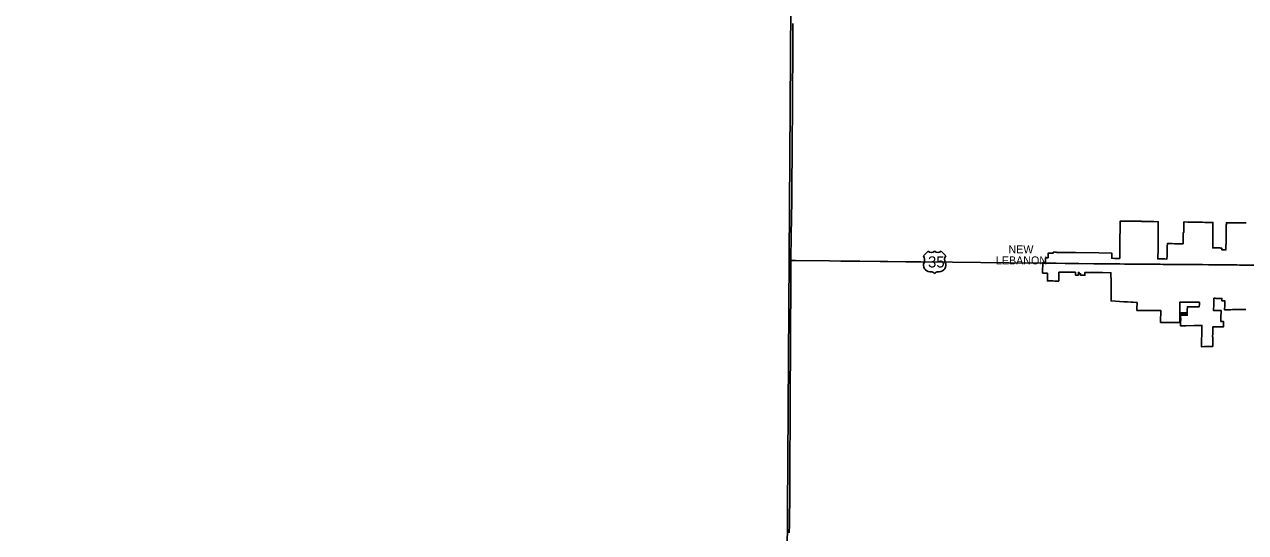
# Model space of a CAD drawing. Extents: x 0 to 34, y 0 to 22.
# Drawn here: x 3.218 to 4.445, y 14.836 to 15.346 of the extents above; entities that cross this region are included whole.
import ezdxf

# ---------------------------------------------------------------- set-up
doc = ezdxf.new("R2010")
doc.units = 0
for name, color, linetype in [('GM_X_Corporation', 7, 'Continuous'), ('GM_X_Corporation_Text', 7, 'Continuous'), ('GM_X_County', 7, 'Continuous'), ('GM_X_US_Location', 7, 'Continuous'), ('GM_X_US_Route', 7, 'Continuous'), ('GM_X_US_Shield', 7, 'Continuous'), ('SC_Scratch1', 7, 'Continuous')]:
    doc.layers.add(name, color=color, linetype=linetype)

msp = doc.modelspace()

# ---------------------------------------------------------------- linework, layer by layer
at = {"layer": 'GM_X_Corporation'}
msp.add_lwpolyline([(4.4448, 15.0596), (4.4439, 15.0596), (4.4411, 15.0596), (4.4405, 15.0596), (4.4388, 15.0595), (4.4359, 15.0595), (4.4347, 15.0595), (4.4316, 15.0595), (4.4296, 15.0594), (4.4268, 15.0594), (4.4242, 15.0594), (4.4235, 15.0594), (4.4236, 15.0597), (4.4237, 15.0632), (4.4237, 15.0647), (4.4238, 15.0678), (4.4238, 15.0682), (4.4235, 15.0682), (4.4233, 15.0682), (4.4208, 15.0683), (4.4208, 15.0683), (4.4209, 15.0707), (4.4198, 15.0707), (4.4186, 15.0708), (4.4181, 15.0708), (4.4175, 15.0708), (4.4163, 15.0708), (4.4152, 15.0708), (4.414, 15.0709), (4.4138, 15.0709), (4.4129, 15.0709), (4.4128, 15.0699), (4.4128, 15.0687), (4.4128, 15.0685), (4.4128, 15.0684), (4.4127, 15.0674), (4.4127, 15.0661), (4.4127, 15.0661), (4.4127, 15.0656), (4.4126, 15.0649), (4.4126, 15.064), (4.4126, 15.0636), (4.4126, 15.0624), (4.4125, 15.0611), (4.4125, 15.0605), (4.4125, 15.0599), (4.4124, 15.0587), (4.4126, 15.0587), (4.4135, 15.0587), (4.4136, 15.0587), (4.4142, 15.0587), (4.415, 15.0587), (4.4158, 15.0587), (4.4166, 15.0587), (4.4174, 15.0587), (4.4187, 15.0587), (4.4201, 15.0587), (4.4201, 15.0587), (4.4201, 15.0587), (4.4201, 15.0585), (4.42, 15.0575), (4.42, 15.0572), (4.42, 15.0571), (4.42, 15.0558), (4.42, 15.0555), (4.4199, 15.054), (4.4199, 15.0531), (4.4199, 15.0523), (4.4199, 15.0511), (4.4198, 15.0507), (4.4198, 15.0498), (4.4198, 15.0489), (4.4198, 15.0474), (4.4198, 15.0474), (4.4209, 15.0474), (4.4213, 15.0474), (4.4225, 15.0474), (4.4226, 15.0474), (4.4225, 15.0423), (4.4223, 15.0423), (4.4206, 15.0423), (4.4193, 15.0423), (4.4192, 15.0423), (4.418, 15.0423), (4.4167, 15.0423), (4.4154, 15.0423), (4.4141, 15.0423), (4.4118, 15.0423), (4.4117, 15.0411), (4.4117, 15.0391), (4.4116, 15.0363), (4.4116, 15.0361), (4.4116, 15.0357), (4.4115, 15.032), (4.4119, 15.032), (4.4118, 15.0299), (4.4117, 15.028), (4.4117, 15.0276), (4.4117, 15.0247), (4.4116, 15.0239), (4.4116, 15.0225), (4.411, 15.0225), (4.4086, 15.0225), (4.4033, 15.0223), (4.4003, 15.0222), (4.4004, 15.0238), (4.4004, 15.0241), (4.4005, 15.0275), (4.4005, 15.0308), (4.4006, 15.0329), (4.4006, 15.0344), (4.4008, 15.0436), (4.4008, 15.0436), (4.3986, 15.0436), (4.3957, 15.0435), (4.3931, 15.0434), (4.3846, 15.0432), (4.3793, 15.0431), (4.3793, 15.0431), (4.3793, 15.0442), (4.3793, 15.045), (4.3794, 15.0466), (4.3794, 15.0469), (4.3795, 15.0495), (4.3795, 15.0504), (4.3794, 15.0518), (4.3795, 15.0533), (4.3795, 15.0537), (4.3795, 15.0538), (4.3819, 15.0538), (4.3851, 15.0538), (4.386, 15.0538), (4.386, 15.0555), (4.3851, 15.0555), (4.3815, 15.0556), (4.3795, 15.0556), (4.3795, 15.0556), (4.3795, 15.0563), (4.3795, 15.0564), (4.3812, 15.0564), (4.3859, 15.0563), (4.3861, 15.0563), (4.3861, 15.0565), (4.3861, 15.0595), (4.3862, 15.062), (4.3862, 15.0624), (4.3881, 15.0624), (4.3895, 15.0624), (4.3933, 15.0624), (4.3968, 15.0624), (4.3981, 15.0624), (4.3981, 15.0627), (4.3981, 15.0633), (4.3981, 15.0635), (4.3982, 15.0638), (4.3982, 15.0649), (4.3982, 15.0653), (4.3982, 15.0661), (4.3982, 15.0669), (4.3972, 15.0669), (4.3963, 15.0669), (4.3954, 15.0669), (4.3947, 15.0669), (4.3941, 15.0669), (4.393, 15.0669), (4.3927, 15.0669), (4.3918, 15.0669), (4.3906, 15.0669), (4.3905, 15.0669), (4.3894, 15.0669), (4.3882, 15.0669), (4.3871, 15.0669), (4.3859, 15.0669), (4.3847, 15.0669), (4.384, 15.0669), (4.3835, 15.0669), (4.3823, 15.067), (4.3812, 15.067), (4.3811, 15.067), (4.3797, 15.067), (4.3792, 15.067), (4.3787, 15.067), (4.3787, 15.0669), (4.3787, 15.0656), (4.3787, 15.0624), (4.3787, 15.0622), (4.3787, 15.0621), (4.3787, 15.0619), (4.3787, 15.0611), (4.3787, 15.0608), (4.3787, 15.0595), (4.3786, 15.0587), (4.3786, 15.0587), (4.3786, 15.0565), (4.3786, 15.0565), (4.3785, 15.055), (4.3785, 15.0544), (4.3785, 15.0537), (4.3785, 15.0533), (4.3785, 15.0525), (4.3785, 15.0518), (4.3785, 15.0504), (4.3785, 15.0495), (4.3785, 15.0494), (4.3785, 15.0494), (4.3785, 15.0494), (4.3785, 15.0488), (4.3785, 15.0488), (4.3785, 15.0482), (4.3785, 15.0482), (4.3785, 15.0482), (4.3784, 15.0466), (4.3767, 15.0466), (4.3761, 15.0466), (4.3754, 15.0466), (4.3747, 15.0466), (4.3741, 15.0466), (4.3733, 15.0466), (4.3729, 15.0466), (4.3724, 15.0466), (4.3714, 15.0466), (4.3706, 15.0466), (4.3687, 15.0466), (4.3663, 15.0466), (4.364, 15.0466), (4.3621, 15.0466), (4.3617, 15.0466), (4.3601, 15.0466), (4.3593, 15.0466), (4.3592, 15.0466), (4.3593, 15.0474), (4.3593, 15.0475), (4.3593, 15.0492), (4.3593, 15.05), (4.3593, 15.0511), (4.3593, 15.0523), (4.3594, 15.0535), (4.3594, 15.0542), (4.3594, 15.0546), (4.3594, 15.0559), (4.3594, 15.0564), (4.3594, 15.0568), (4.3594, 15.0587), (4.3594, 15.0587), (4.3587, 15.0587), (4.3569, 15.0587), (4.3548, 15.0587), (4.3527, 15.0587), (4.3519, 15.0587), (4.3504, 15.0587), (4.3492, 15.0587), (4.348, 15.0587), (4.3462, 15.0587), (4.3449, 15.0587), (4.3446, 15.0587), (4.3401, 15.0587), (4.3385, 15.0587), (4.3355, 15.0587), (4.3355, 15.0629), (4.3355, 15.0634), (4.3356, 15.0636), (4.3356, 15.0649), (4.3356, 15.0659), (4.3356, 15.0666), (4.3356, 15.0666), (4.3354, 15.0666), (4.3354, 15.0667), (4.3349, 15.0667), (4.3349, 15.0667), (4.3317, 15.0669), (4.3296, 15.067), (4.3259, 15.0672), (4.3223, 15.0674), (4.3095, 15.0682), (4.3095, 15.0771), (4.3095, 15.0893), (4.3095, 15.0901), (4.3094, 15.093), (4.3094, 15.095), (4.3094, 15.0966), (4.3011, 15.0967), (4.301, 15.0967), (4.2927, 15.0968), (4.2893, 15.0968), (4.2892, 15.0968), (4.2832, 15.0969), (4.2832, 15.0967), (4.2832, 15.094), (4.2791, 15.094), (4.2789, 15.094), (4.2789, 15.0953), (4.2789, 15.0955), (4.2776, 15.0955), (4.2775, 15.0955), (4.2775, 15.0963), (4.2775, 15.0968), (4.2775, 15.0969), (4.2774, 15.0969), (4.2771, 15.0969), (4.277, 15.0969), (4.2767, 15.097), (4.2767, 15.097), (4.2767, 15.0968), (4.2767, 15.0963), (4.2767, 15.0941), (4.2766, 15.0941), (4.2738, 15.0941), (4.2738, 15.0969), (4.2738, 15.097), (4.2733, 15.097), (4.2732, 15.097), (4.2699, 15.097), (4.2699, 15.097), (4.2679, 15.097), (4.2663, 15.097), (4.2663, 15.097), (4.2572, 15.0971), (4.2572, 15.097), (4.2572, 15.0967), (4.2572, 15.0963), (4.2571, 15.0925), (4.257, 15.0882), (4.2534, 15.0882), (4.253, 15.0882), (4.2509, 15.0883), (4.2504, 15.0883), (4.2499, 15.0883), (4.2456, 15.0883), (4.2457, 15.0951), (4.2457, 15.0961), (4.2427, 15.0961), (4.2426, 15.0961), (4.2408, 15.0962), (4.2407, 15.0962), (4.2408, 15.098), (4.241, 15.1056), (4.241, 15.1057), (4.241, 15.1062), (4.241, 15.1068), (4.2436, 15.1068), (4.2437, 15.1116), (4.2442, 15.1116), (4.2451, 15.1116), (4.2463, 15.1116), (4.2463, 15.112), (4.2464, 15.1162), (4.2464, 15.1163), (4.2465, 15.1163), (4.2476, 15.1163), (4.2503, 15.1163), (4.2514, 15.1163), (4.2514, 15.117), (4.2514, 15.1171), (4.2541, 15.1171), (4.2545, 15.1171), (4.255, 15.117), (4.2576, 15.117), (4.2585, 15.117), (4.2636, 15.1169), (4.2646, 15.1169), (4.2647, 15.1169), (4.2657, 15.1169), (4.2668, 15.1169), (4.2678, 15.1169), (4.2699, 15.1168), (4.2726, 15.1168), (4.2739, 15.1168), (4.2971, 15.1165), (4.3103, 15.1163), (4.3103, 15.1162), (4.3103, 15.1162), (4.3102, 15.111), (4.3106, 15.111), (4.3131, 15.1109), (4.3146, 15.1109), (4.3147, 15.1109), (4.3163, 15.1109), (4.3182, 15.1109), (4.3182, 15.112), (4.3184, 15.1215), (4.3184, 15.124), (4.3184, 15.1269), (4.3185, 15.1294), (4.3185, 15.1311), (4.3185, 15.1344), (4.3186, 15.1374), (4.3186, 15.1413), (4.3186, 15.1429), (4.3187, 15.1459), (4.3187, 15.1481), (4.3187, 15.1484), (4.3192, 15.1484), (4.3228, 15.1484), (4.3244, 15.1484), (4.3263, 15.1483), (4.3287, 15.1483), (4.329, 15.1483), (4.3298, 15.1483), (4.3329, 15.1483), (4.3352, 15.1483), (4.3381, 15.1482), (4.34, 15.1482), (4.34, 15.1482), (4.34, 15.1482), (4.34, 15.1481), (4.34, 15.1481), (4.3432, 15.148), (4.3439, 15.148), (4.3477, 15.148), (4.3493, 15.1479), (4.3525, 15.1479), (4.357, 15.1478), (4.357, 15.1478), (4.3569, 15.1405), (4.3568, 15.1359), (4.3568, 15.1351), (4.3568, 15.1324), (4.3568, 15.1309), (4.3567, 15.1212), (4.3567, 15.1209), (4.3565, 15.1105), (4.3565, 15.1104), (4.3565, 15.1104), (4.3601, 15.1104), (4.3602, 15.1104), (4.363, 15.1104), (4.3634, 15.1104), (4.3657, 15.1103), (4.3658, 15.114), (4.3658, 15.1151), (4.3659, 15.1181), (4.366, 15.1211), (4.366, 15.1229), (4.3661, 15.1258), (4.371, 15.1258), (4.3732, 15.1257), (4.3749, 15.1257), (4.3776, 15.1257), (4.3803, 15.1256), (4.3815, 15.1256), (4.3816, 15.1256), (4.3818, 15.1256), (4.3819, 15.1256), (4.382, 15.1369), (4.3823, 15.1369), (4.3826, 15.1369), (4.3826, 15.1415), (4.3827, 15.1475), (4.383, 15.1475), (4.3831, 15.1475), (4.3867, 15.1474), (4.3882, 15.1474), (4.3898, 15.1474), (4.3916, 15.1473), (4.3956, 15.1473), (4.3972, 15.1472), (4.3973, 15.1472), (4.3982, 15.1472), (4.4012, 15.1472), (4.4036, 15.1471), (4.4091, 15.1471), (4.4119, 15.147), (4.4119, 15.1469), (4.4119, 15.1464), (4.4119, 15.142), (4.4118, 15.1355), (4.4118, 15.1345), (4.4118, 15.1324), (4.4118, 15.1322), (4.4118, 15.1289), (4.4118, 15.1282), (4.4118, 15.1251), (4.4117, 15.1214), (4.4119, 15.1214), (4.4125, 15.1214), (4.4127, 15.1214), (4.4135, 15.1214), (4.4139, 15.1214), (4.4142, 15.1214), (4.4143, 15.1214), (4.4151, 15.1214), (4.4159, 15.1214), (4.4167, 15.1214), (4.4171, 15.1214), (4.4174, 15.1214), (4.4175, 15.1214), (4.4183, 15.1214), (4.4191, 15.1214), (4.4195, 15.1213), (4.4199, 15.1213), (4.4207, 15.1213), (4.4207, 15.1213), (4.4207, 15.1196), (4.4216, 15.1196), (4.4219, 15.1196), (4.4231, 15.1195), (4.4248, 15.1195), (4.4248, 15.1222), (4.4249, 15.1229), (4.4249, 15.1229), (4.4249, 15.1241), (4.4249, 15.1248), (4.425, 15.1249), (4.425, 15.1257), (4.425, 15.1262), (4.425, 15.1271), (4.425, 15.1292), (4.4251, 15.1311), (4.4251, 15.1322), (4.4251, 15.1333), (4.4251, 15.1336), (4.4251, 15.1365), (4.4251, 15.1379), (4.4252, 15.1414), (4.4252, 15.1433), (4.4252, 15.1444), (4.4253, 15.1452), (4.4253, 15.1468), (4.4293, 15.1468), (4.4301, 15.1468), (4.4347, 15.1467), (4.4367, 15.1467), (4.4389, 15.1467), (4.4436, 15.1466), (4.4452, 15.1466)], dxfattribs=at)
msp.add_lwpolyline([(4.4119, 15.147), (4.4119, 15.147), (4.4119, 15.147)], close=True, dxfattribs=at)
at = {"layer": 'GM_X_County'}
msp.add_lwpolyline([(3.9864, 14.8354), (3.9864, 14.8363), (3.9864, 14.8371), (3.9864, 14.8385), (3.9865, 14.8403), (3.9865, 14.8413), (3.9865, 14.8445), (3.9866, 14.848), (3.9866, 14.8504), (3.9866, 14.8523), (3.9866, 14.8525), (3.9866, 14.853), (3.9867, 14.8548), (3.9867, 14.8566), (3.9867, 14.858), (3.9867, 14.8592), (3.9868, 14.8606), (3.9868, 14.8615), (3.9868, 14.862), (3.9868, 14.8647), (3.9868, 14.8658), (3.9868, 14.8681), (3.9869, 14.8695), (3.9869, 14.8715), (3.9869, 14.8752), (3.9869, 14.8782), (3.9869, 14.8818), (3.9869, 14.8828), (3.9869, 14.8841), (3.9869, 14.8861), (3.9869, 14.8877), (3.9869, 14.8894), (3.9869, 14.8903), (3.9869, 14.8915), (3.9869, 14.8931), (3.9869, 14.8946), (3.9869, 14.895), (3.9869, 14.8978), (3.9869, 14.8987), (3.987, 14.9005), (3.987, 14.9018), (3.987, 14.903), (3.987, 14.9042), (3.987, 14.9054), (3.987, 14.9066), (3.987, 14.9072), (3.987, 14.9087), (3.987, 14.9104), (3.987, 14.9127), (3.987, 14.9152), (3.987, 14.9174), (3.9871, 14.9223), (3.9871, 14.9235), (3.9871, 14.9251), (3.9871, 14.927), (3.9872, 14.9292), (3.9872, 14.9317), (3.9872, 14.9326), (3.9872, 14.9341), (3.9872, 14.9354), (3.9872, 14.9365), (3.9872, 14.9389), (3.9872, 14.9397), (3.9872, 14.9414), (3.9872, 14.9426), (3.9872, 14.9434), (3.9872, 14.9449), (3.9872, 14.9461), (3.9872, 14.947), (3.9873, 14.9488), (3.9873, 14.9506), (3.9873, 14.9521), (3.9873, 14.953), (3.9873, 14.9542), (3.9873, 14.9554), (3.9873, 14.9571), (3.9873, 14.9591), (3.9873, 14.9599), (3.9873, 14.962), (3.9873, 14.9638), (3.9873, 14.9643), (3.9873, 14.9653), (3.9873, 14.9671), (3.9874, 14.9683), (3.9874, 14.9698), (3.9874, 14.971), (3.9874, 14.9722), (3.9874, 14.9734), (3.9874, 14.9744), (3.9874, 14.9756), (3.9874, 14.9767), (3.9874, 14.9777), (3.9874, 14.9787), (3.9874, 14.9797), (3.9874, 14.9798), (3.9874, 14.98), (3.9874, 14.9802), (3.9874, 14.9811), (3.9874, 14.9818), (3.9874, 14.9845), (3.9874, 14.9862), (3.9874, 14.9879), (3.9874, 14.9891), (3.9874, 14.9913), (3.9874, 14.9927), (3.9874, 14.9957), (3.9874, 14.9969), (3.9875, 14.9986), (3.9875, 14.9998), (3.9875, 15.0005), (3.9875, 15.0025), (3.9875, 15.0038), (3.9875, 15.0047), (3.9876, 15.0065), (3.9876, 15.0081), (3.9876, 15.0092), (3.9876, 15.011), (3.9876, 15.0127), (3.9876, 15.0139), (3.9876, 15.0154), (3.9876, 15.0164), (3.9876, 15.0186), (3.9877, 15.0206), (3.9877, 15.022), (3.9876, 15.0239), (3.9876, 15.0255), (3.9876, 15.0283), (3.9876, 15.0304), (3.9876, 15.0313), (3.9876, 15.0333), (3.9876, 15.035), (3.9876, 15.0361), (3.9876, 15.0382), (3.9876, 15.0394), (3.9876, 15.0425), (3.9876, 15.0434), (3.9877, 15.0453), (3.9877, 15.0471), (3.9877, 15.0518), (3.9877, 15.0532), (3.9877, 15.0546), (3.9877, 15.0558), (3.9877, 15.0568), (3.9877, 15.0586), (3.9877, 15.0598), (3.9878, 15.0605), (3.9878, 15.0633), (3.9878, 15.065), (3.9878, 15.0658), (3.9878, 15.0677), (3.9878, 15.0699), (3.9878, 15.0738), (3.9878, 15.0747), (3.9878, 15.0757), (3.9878, 15.0764), (3.9878, 15.0772), (3.9878, 15.079), (3.9878, 15.0803), (3.9878, 15.0815), (3.9879, 15.0838), (3.9879, 15.0859), (3.9879, 15.0875), (3.9879, 15.089), (3.9879, 15.0905), (3.988, 15.0952), (3.988, 15.0988), (3.988, 15.1041), (3.988, 15.106), (3.988, 15.1073), (3.988, 15.109), (3.988, 15.1101), (3.988, 15.1114), (3.988, 15.1128), (3.9881, 15.1142), (3.9881, 15.1163), (3.9881, 15.1173), (3.9881, 15.12), (3.9882, 15.124), (3.9882, 15.1247), (3.9882, 15.1265), (3.9882, 15.1279), (3.9882, 15.1291), (3.9883, 15.1339), (3.9884, 15.1388), (3.9884, 15.1405), (3.9884, 15.1421), (3.9885, 15.1435), (3.9885, 15.1461), (3.9885, 15.1469), (3.9886, 15.149), (3.9886, 15.1508), (3.9886, 15.155), (3.9887, 15.1563), (3.9887, 15.1582), (3.9888, 15.1621), (3.9888, 15.1671), (3.9888, 15.1701), (3.9889, 15.1718), (3.9889, 15.1742), (3.9889, 15.1765), (3.9889, 15.1773), (3.9889, 15.1819), (3.989, 15.1846), (3.989, 15.1868), (3.989, 15.1895), (3.989, 15.1906), (3.989, 15.1933), (3.989, 15.1938), (3.9891, 15.1946), (3.9891, 15.1955), (3.9891, 15.198), (3.9891, 15.1994), (3.9891, 15.2004), (3.9892, 15.2023), (3.9892, 15.2042), (3.9892, 15.2059), (3.9892, 15.2076), (3.9892, 15.2086), (3.9892, 15.2106), (3.9892, 15.212), (3.9893, 15.2142), (3.9893, 15.2148), (3.9893, 15.2168), (3.9893, 15.2185), (3.9893, 15.2212), (3.9893, 15.2232), (3.9893, 15.228), (3.9894, 15.2324), (3.9894, 15.2366), (3.9894, 15.2414), (3.9894, 15.2433), (3.9895, 15.2454), (3.9895, 15.2465), (3.9895, 15.2506), (3.9895, 15.252), (3.9895, 15.2539), (3.9895, 15.2556), (3.9895, 15.2574), (3.9896, 15.2589), (3.9896, 15.2596), (3.9896, 15.2629), (3.9896, 15.2664), (3.9896, 15.2713), (3.9897, 15.2735), (3.9897, 15.2751), (3.9897, 15.2776), (3.9897, 15.2793), (3.9897, 15.2799), (3.9897, 15.2816), (3.9897, 15.2833), (3.9897, 15.2846), (3.9897, 15.2859), (3.9897, 15.2897), (3.9897, 15.2912), (3.9897, 15.2931), (3.9897, 15.2959), (3.9898, 15.2978), (3.9898, 15.2997), (3.9898, 15.3019), (3.9898, 15.3034), (3.9898, 15.3053), (3.9898, 15.3065), (3.9898, 15.3093), (3.9898, 15.311), (3.9898, 15.315), (3.9898, 15.3169), (3.9898, 15.3177), (3.9898, 15.3192), (3.9898, 15.3212), (3.9899, 15.323), (3.9899, 15.3264), (3.9899, 15.3301), (3.9899, 15.3323), (3.9899, 15.3336), (3.9899, 15.3348), (3.9899, 15.3381), (3.9899, 15.3403), (3.9899, 15.3422), (3.9899, 15.3441), (3.99, 15.3467)], dxfattribs=at)
at = {"layer": 'GM_X_US_Route'}
for p, q in [((4.0778, 15.1079), (4.0852, 15.1078)), ((4.2399, 15.1062), (4.2507, 15.1061)), ((4.2507, 15.1061), (4.2543, 15.106)), ((4.3297, 15.1053), (4.3357, 15.1052)), ((4.3792, 15.1048), (4.3815, 15.1047))]:
    msp.add_line(p, q, dxfattribs=at)
for points in [[(3.9881, 15.1089), (3.9927, 15.1088), (4.0267, 15.1084), (4.0381, 15.1083), (4.0424, 15.1083), (4.0573, 15.1081), (4.0778, 15.1079)], [(4.0852, 15.1078), (4.1036, 15.1076), (4.1184, 15.1074), (4.1504, 15.1071), (4.2068, 15.1065), (4.2399, 15.1062)], [(4.2543, 15.106), (4.2636, 15.1059), (4.2701, 15.1059), (4.2733, 15.1059), (4.2772, 15.1059), (4.2921, 15.1056), (4.2965, 15.1056), (4.3001, 15.1056)], [(4.3001, 15.1056), (4.3038, 15.1055), (4.3069, 15.1055), (4.3121, 15.1054), (4.3184, 15.1054), (4.323, 15.1053), (4.3297, 15.1053)], [(4.3357, 15.1052), (4.3423, 15.1051), (4.3529, 15.1051), (4.358, 15.105), (4.3587, 15.105)], [(4.3587, 15.105), (4.362, 15.1049), (4.3681, 15.1049), (4.3749, 15.1048), (4.3792, 15.1048)], [(4.3815, 15.1047), (4.3869, 15.1047), (4.3919, 15.1047)], [(4.3919, 15.1047), (4.3959, 15.1047), (4.4011, 15.1047), (4.4013, 15.1047)], [(4.4013, 15.1047), (4.4073, 15.1046), (4.4098, 15.1046), (4.4139, 15.1046), (4.4198, 15.1045), (4.4247, 15.1045), (4.4304, 15.1044), (4.431, 15.1045), (4.436, 15.1044), (4.4386, 15.1043)], [(4.4386, 15.1043), (4.4441, 15.1043), (4.4476, 15.1043), (4.4521, 15.1042), (4.463, 15.1041)]]:
    msp.add_lwpolyline(points, dxfattribs=at)
at = {"layer": 'GM_X_US_Shield'}
for p, q in [((4.1258, 15.1181), (4.1212, 15.1135)), ((4.1436, 15.1135), (4.1389, 15.1181)), ((4.1277, 15.0976), (4.1286, 15.0976)), ((4.1361, 15.0976), (4.137, 15.0976))]:
    msp.add_line(p, q, dxfattribs=at)
for centre, radius, start, end in [((4.1158, 15.1097), 0.00653, 334.5471, 35.0009), ((4.1291, 15.1214), 0.00466, 225.573, 314.427), ((4.1356, 15.1214), 0.00466, 225.573, 314.427), ((4.1489, 15.1097), 0.00653, 144.9991, 205.4529), ((4.1276, 15.1041), 0.00653, 154.8319, 270.6383), ((4.1286, 15.0929), 0.00466, 36.8699, 90), ((4.1361, 15.0929), 0.00466, 90, 143.1301), ((4.1371, 15.1041), 0.00653, 269.3617, 25.1681)]:
    msp.add_arc(centre, radius, start, end, dxfattribs=at)
at = {"layer": 'SC_Scratch1'}
msp.add_lwpolyline([(3.9803, 14.1988), (3.9931, 16.126), (3.3837, 16.1299), (3.2897, 16.1315), (2.8882, 16.1402)], dxfattribs=at)

# ---------------------------------------------------------------- texts
at = {"layer": 'GM_X_Corporation_Text'}
for s, p in [('NEW', (4.2065, 15.116)), ('LEBANON', (4.1939, 15.1049))]:
    msp.add_text(s, height=0.00804, rotation=0, dxfattribs=at).set_placement(p)
at = {"layer": 'GM_X_US_Location'}
msp.add_text('35', height=0.0000161, rotation=0, dxfattribs=at).set_placement((4.129, 15.104))
for s in ['0', '/']:
    msp.add_text(s, height=0.0000161, dxfattribs=at).set_placement((4.1324, 15.1073))
at = {"layer": 'GM_X_US_Shield'}
msp.add_text('35', height=0.01119, dxfattribs=at).set_placement((4.1257, 15.1018))

doc.saveas('drawing.dxf')
